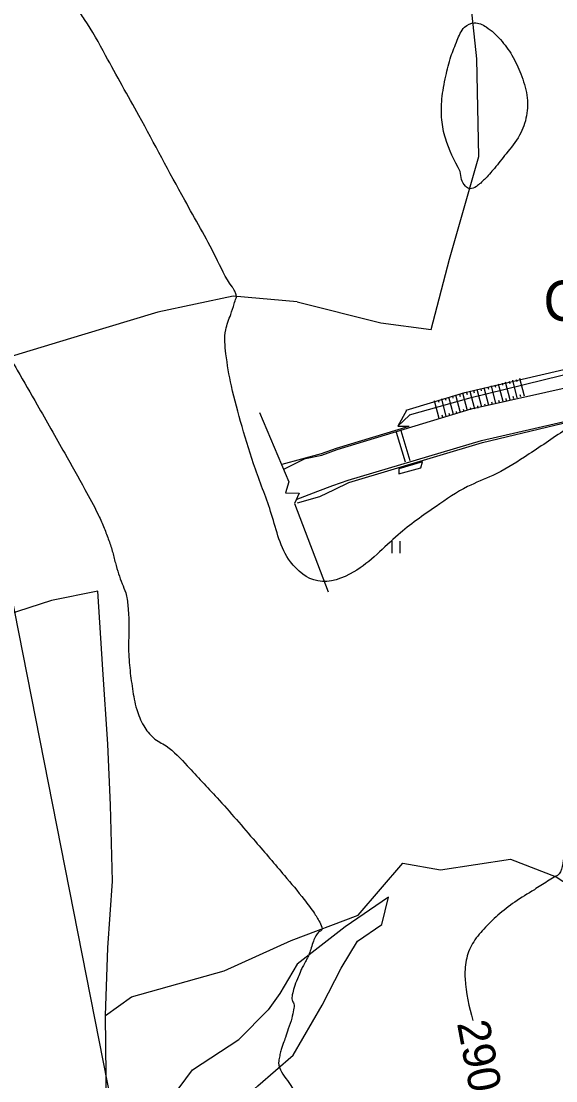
# Model space of a CAD drawing. Extents: x -475575 to -473225, y -1116053 to -1114104.
# Drawn here: x -474438.2 to -474372, y -1114570.2 to -1114439 of the extents above; entities that cross this region are included whole.
import ezdxf

# ---------------------------------------------------------------- set-up
doc = ezdxf.new("R2010")
doc.units = 0
for name, color, linetype in [('Budovy', 7, 'Continuous'), ('cesty', 7, 'Continuous'), ('hrana_P', 7, 'Continuous'), ('pam__tka', 7, 'Continuous'), ('TP_HS', 7, 'Continuous'), ('Vrstevnice_hlavni', 7, 'Continuous'), ('Vrstevnice_popis', 7, 'Continuous'), ('Vrstevnice_vedlejsi', 7, 'Continuous'), ('Vrstva_10', 7, 'Continuous')]:
    doc.layers.add(name, color=color, linetype=linetype)

msp = doc.modelspace()

# ---------------------------------------------------------------- linework, layer by layer
msp.add_lwpolyline([(-474182.626466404, -1115811.6046355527), (-473891.2432688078, -1115754.1169659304), (-474175.77819926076, -1114311.9173010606), (-474467.1613968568, -1114369.4049706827)], close=True)
at = {"layer": 'Budovy'}
msp.add_lwpolyline([(-474408.6644094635, -1114487.462002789), (-474405.0206297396, -1114496.0347098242), (-474405.46910377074, -1114497.4175296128), (-474403.7775642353, -1114497.4403683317), (-474404.3242316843, -1114498.727380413), (-474400.1589070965, -1114509.6549173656)], dxfattribs=at)
at = {"layer": 'cesty'}
for p, q in [((-474391.5530898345, -1114489.1814863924), (-474390.14101885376, -1114489.1419196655)), ((-474400.9560000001, -1114492.753), (-474399.05700000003, -1114492.0660000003)), ((-474402.9630000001, -1114493.158), (-474400.9560000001, -1114492.753)), ((-474402.9630000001, -1114493.158), (-474402.9630000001, -1114493.158)), ((-474399.402, -1114496.983), (-474397.609, -1114496.132)), ((-474401.18200000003, -1114497.8600000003), (-474399.402, -1114496.983)), ((-474403.96950800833, -1114498.639742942), (-474401.18200000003, -1114497.8600000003))]:
    msp.add_line(p, q, dxfattribs=at)
for points in [[(-474390.5118018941, -1114487.1961753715), (-474383.2441160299, -1114485.0014103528), (-474364.44700000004, -1114480.627)], [(-474364.32800000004, -1114481.217), (-474382.8100104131, -1114485.7461660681), (-474390.14775582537, -1114487.8018328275)], [(-474399.05700000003, -1114492.0660000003), (-474382.49493628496, -1114487.0226715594), (-474363.99100000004, -1114482.889)], [(-474380.28498984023, -1114486.5844812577), (-474380.8555120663, -1114484.4056765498)], [(-474380.41640151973, -1114484.2906950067), (-474380.3450862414, -1114484.5630455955)], [(-474379.40676874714, -1114486.3545181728), (-474379.9772909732, -1114484.1757134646)], [(-474379.5381804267, -1114484.0607319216), (-474379.4668651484, -1114484.3330825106)], [(-474378.528547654, -1114486.1245550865), (-474379.09906988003, -1114483.9457503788)], [(-474378.65995933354, -1114483.8307688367), (-474378.5886440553, -1114484.1031194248)], [(-474377.65032656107, -1114485.8945920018), (-474378.22084878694, -1114483.7157872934)], [(-474377.78173824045, -1114483.6008057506), (-474377.7104229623, -1114483.8731563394)], [(-474376.77210546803, -1114485.6646289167), (-474377.34262769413, -1114483.4858242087)], [(-474376.90351714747, -1114483.3708426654), (-474376.8322018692, -1114483.6431932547)], [(-474375.89388437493, -1114485.4346658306), (-474376.464406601, -1114483.2558611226)], [(-474385.6857280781, -1114485.6704735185), (-474385.61441279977, -1114485.9428241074)], [(-474384.6760953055, -1114487.7342966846), (-474385.2466175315, -1114485.5554919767)], [(-474384.80750698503, -1114485.4405104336), (-474384.7361917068, -1114485.7128610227)], [(-474383.7978742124, -1114487.5043335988), (-474384.3683964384, -1114485.3255288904)], [(-474383.92928589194, -1114485.2105473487), (-474383.8579706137, -1114485.4828979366)], [(-474382.9196531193, -1114487.2743705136), (-474383.49017534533, -1114485.0955658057)], [(-474383.05106479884, -1114484.9805842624), (-474382.9797495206, -1114485.2529348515)], [(-474382.0414320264, -1114487.0444074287), (-474382.6119542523, -1114484.8656027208)], [(-474382.17284370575, -1114484.7506211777), (-474382.1015284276, -1114485.0229717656)], [(-474381.16321093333, -1114486.8144443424), (-474381.73373315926, -1114484.6356396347)], [(-474381.29462261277, -1114484.5206580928), (-474381.2233073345, -1114484.7930086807)], [(-474378.0894371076, -1114486.0095735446), (-474378.16075238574, -1114485.7372229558)], [(-474377.2112160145, -1114485.7796104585), (-474377.28253129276, -1114485.5072598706)], [(-474376.3329949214, -1114485.5496473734), (-474376.40431019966, -1114485.2772967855)], [(-474397.715, -1114495.834), (-474381.1846396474, -1114490.937751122), (-474363.201, -1114486.811)], [(-474397.609, -1114496.132), (-474381.09452447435, -1114491.169170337), (-474363.188, -1114486.8730000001)], [(-474386.4325374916, -1114488.1942228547), (-474387.0030597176, -1114486.0154181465)], [(-474386.5639491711, -1114485.9004366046), (-474386.4926338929, -1114486.1727871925)], [(-474385.55431639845, -1114487.9642597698), (-474386.1248386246, -1114485.7854550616)], [(-474382.4805425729, -1114487.1593889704), (-474382.55185785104, -1114486.8870383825)], [(-474381.6023214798, -1114486.9294258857), (-474381.67363675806, -1114486.6570752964)], [(-474380.7241003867, -1114486.6994628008), (-474380.79541566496, -1114486.4271122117)], [(-474379.8458792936, -1114486.4694997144), (-474379.917194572, -1114486.1971491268)], [(-474378.9676582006, -1114486.2395366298), (-474379.0389734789, -1114485.9671860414)], [(-474390.4945073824, -1114487.2188734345), (-474391.5530898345, -1114489.1814863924), (-474390.12851488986, -1114487.8025076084)], [(-474385.9934269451, -1114488.0792413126), (-474386.06474222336, -1114487.8068907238)], [(-474385.11520585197, -1114487.8492782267), (-474385.1865211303, -1114487.5769276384)], [(-474384.236984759, -1114487.6193151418), (-474384.3083000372, -1114487.3469645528)], [(-474383.3587636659, -1114487.3893520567), (-474383.43007894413, -1114487.1170014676)], [(-474405.8515442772, -1114493.8510337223), (-474401.0100955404, -1114492.559884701), (-474399.1201915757, -1114491.8761753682), (-474390.14101885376, -1114489.1419196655)], [(-474399.57700000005, -1114496.507), (-474397.715, -1114495.834)], [(-474404.128962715, -1114498.2366301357), (-474401.43200000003, -1114497.199)], [(-474401.43200000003, -1114497.199), (-474399.57700000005, -1114496.507)]]:
    msp.add_lwpolyline(points, dxfattribs=at)
at = {"layer": 'hrana_P'}
msp.add_lwpolyline([(-474402.9630000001, -1114493.158), (-474405.61337955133, -1114494.4839191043)], dxfattribs=at)
at = {"layer": 'pam__tka'}
for p, q in [((-474390.6075392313, -1114493.6333155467), (-474391.7283912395, -1114489.9261577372)), ((-474390.0332159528, -1114493.459670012), (-474391.154067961, -1114489.7525122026))]:
    msp.add_line(p, q, dxfattribs=at)
msp.add_lwpolyline([(-474391.4259391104, -1114494.4299316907), (-474391.4259391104, -1114495.0529834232), (-474388.7172134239, -1114494.3364739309), (-474388.50816562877, -1114493.5888118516)], close=True, dxfattribs=at)
at = {"layer": 'Vrstevnice_hlavni'}
for points in [[(-474314.4652568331, -1114423.5624916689), (-474315.15, -1114426.169), (-474316.163, -1114431.774), (-474317.369, -1114436.945), (-474318.766, -1114441.6800000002), (-474320.35400000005, -1114445.9810000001), (-474321.972, -1114449.681), (-474323.617, -1114452.78), (-474325.291, -1114455.277), (-474326.74100000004, -1114457.9300000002), (-474327.967, -1114460.736), (-474328.96900000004, -1114463.698), (-474329.84400000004, -1114466.1400000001), (-474330.59300000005, -1114468.063), (-474331.215, -1114469.466), (-474332.08400000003, -1114471.237), (-474333.19800000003, -1114473.375), (-474334.559, -1114475.8800000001), (-474336.125, -1114478.272), (-474337.896, -1114480.55), (-474339.87200000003, -1114482.7140000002), (-474341.606, -1114484.4710000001), (-474343.097, -1114485.82), (-474344.34500000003, -1114486.761), (-474345.39900000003, -1114487.69), (-474346.25800000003, -1114488.605), (-474346.922, -1114489.5080000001), (-474348.744, -1114492.982), (-474351.72400000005, -1114499.027), (-474355.862, -1114507.6430000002), (-474358.802, -1114513.52), (-474360.543, -1114516.658), (-474361.086, -1114517.057), (-474361.549, -1114517.367), (-474361.93200000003, -1114517.5890000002), (-474362.234, -1114517.723), (-474362.69200000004, -1114518.027), (-474363.30600000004, -1114518.5010000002), (-474364.075, -1114519.145), (-474364.359, -1114519.9980000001), (-474364.157, -1114521.0590000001), (-474363.46900000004, -1114522.3290000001), (-474364.041, -1114525.543), (-474365.87200000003, -1114530.7), (-474368.962, -1114537.801), (-474371.03, -1114542.537), (-474372.07700000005, -1114544.908), (-474372.101, -1114544.915), (-474372.13, -1114544.928), (-474372.16400000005, -1114544.948), (-474372.20200000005, -1114544.975), (-474373.03500000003, -1114545.5050000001), (-474374.661, -1114546.538), (-474377.082, -1114548.074), (-474379.16500000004, -1114549.699), (-474380.91000000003, -1114551.414), (-474382.31700000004, -1114553.219), (-474383.09300000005, -1114555.2780000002), (-474383.239, -1114557.591), (-474382.271, -1114562.7280000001)], [(-474496.71900000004, -1114442.414), (-474488.08, -1114444.274), (-474485.004, -1114444.8660000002), (-474483.172, -1114445.12), (-474482.58300000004, -1114445.036), (-474481.96300000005, -1114444.972), (-474481.31200000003, -1114444.9270000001), (-474480.629, -1114444.9030000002), (-474479.207, -1114445.301), (-474477.044, -1114446.121), (-474474.14200000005, -1114447.364), (-474472.06200000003, -1114448.208), (-474470.804, -1114448.655), (-474470.369, -1114448.703), (-474467.59, -1114451.1330000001), (-474462.465, -1114455.9440000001), (-474454.99600000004, -1114463.136), (-474449.324, -1114468.739), (-474445.45, -1114472.754), (-474443.373, -1114475.181), (-474441.797, -1114477.129), (-474440.723, -1114478.598), (-474440.15, -1114479.588), (-474438.634, -1114482.234), (-474436.17500000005, -1114486.5350000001), (-474432.77300000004, -1114492.493), (-474430.272, -1114496.986), (-474428.67100000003, -1114500.017), (-474427.971, -1114501.583), (-474427.375, -1114503.117), (-474426.884, -1114504.619), (-474426.498, -1114506.088), (-474426.09300000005, -1114507.438), (-474425.669, -1114508.669), (-474425.226, -1114509.781), (-474424.945, -1114511.439), (-474424.826, -1114513.6430000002), (-474424.869, -1114516.392), (-474424.723, -1114519.071), (-474424.38700000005, -1114521.6800000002), (-474423.862, -1114524.218), (-474422.993, -1114526.242), (-474421.77900000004, -1114527.7510000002), (-474420.221, -1114528.746), (-474417.601, -1114531.217), (-474413.919, -1114535.163), (-474409.17500000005, -1114540.584), (-474405.582, -1114544.781), (-474403.14200000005, -1114547.754), (-474401.85400000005, -1114549.504), (-474401.12600000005, -1114550.762), (-474400.957, -1114551.529), (-474401.348, -1114551.8050000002), (-474401.696, -1114552.2680000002), (-474402, -1114552.919), (-474402.261, -1114553.757), (-474402.509, -1114554.453), (-474402.745, -1114555.006), (-474402.967, -1114555.416), (-474403.157, -1114555.7650000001), (-474403.31200000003, -1114556.051), (-474403.435, -1114556.276), (-474403.655, -1114556.786), (-474403.97400000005, -1114557.5820000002), (-474404.39200000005, -1114558.665), (-474404.607, -1114559.537), (-474404.62, -1114560.2010000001), (-474404.43000000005, -1114560.656), (-474404.44700000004, -1114561.402), (-474404.672, -1114562.441), (-474405.10400000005, -1114563.772), (-474405.455, -1114564.8190000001), (-474405.72500000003, -1114565.584), (-474405.91400000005, -1114566.066), (-474406.07200000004, -1114566.622), (-474406.2, -1114567.252), (-474406.298, -1114567.956), (-474405.21300000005, -1114570.172), (-474402.944, -1114573.899), (-474399.493, -1114579.138), (-474397.21800000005, -1114582.867), (-474396.119, -1114585.085), (-474396.19700000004, -1114585.7920000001), (-474396.238, -1114586.281), (-474396.243, -1114586.551), (-474396.212, -1114586.602), (-474396.19100000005, -1114586.638), (-474396.179, -1114586.6570000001), (-474396.177, -1114586.6600000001), (-474396.17600000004, -1114586.665), (-474396.17600000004, -1114586.673), (-474396.17600000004, -1114586.6840000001), (-474396.172, -1114586.689), (-474396.16400000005, -1114586.689), (-474396.152, -1114586.683), (-474395.809, -1114586.673), (-474395.136, -1114586.6600000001)]]:
    msp.add_spline(points, degree=3, dxfattribs=at)
at = {"layer": 'Vrstevnice_vedlejsi'}
for points in [[(-474327.64059357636, -1114407.3937584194), (-474328.603, -1114410.163), (-474331.498, -1114418.235), (-474335.64400000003, -1114429.118), (-474339.003, -1114437.261), (-474341.575, -1114442.664), (-474343.36100000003, -1114445.328), (-474344.701, -1114447.548), (-474345.596, -1114449.324), (-474346.047, -1114450.656), (-474347.707, -1114454.61), (-474350.57700000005, -1114461.188), (-474354.656, -1114470.389), (-474357.396, -1114476.561), (-474358.797, -1114479.703), (-474358.858, -1114479.815), (-474358.928, -1114479.922), (-474359.00800000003, -1114480.0250000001), (-474359.096, -1114480.122), (-474359.174, -1114480.2010000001), (-474359.24100000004, -1114480.261), (-474359.297, -1114480.304), (-474359.34500000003, -1114480.345), (-474359.38300000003, -1114480.386), (-474359.413, -1114480.4270000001), (-474359.495, -1114480.583), (-474359.629, -1114480.854), (-474359.814, -1114481.2410000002), (-474361.79500000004, -1114482.862), (-474365.571, -1114485.716), (-474371.14300000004, -1114489.8050000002), (-474375.891, -1114492.9880000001), (-474379.81700000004, -1114495.267), (-474382.92000000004, -1114496.6400000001), (-474386.819, -1114499.0890000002), (-474391.515, -1114502.6130000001), (-474397.00800000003, -1114507.212), (-474401.449, -1114508.3220000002), (-474404.83800000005, -1114505.943), (-474407.17500000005, -1114500.0760000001), (-474409.173, -1114494.493), (-474410.831, -1114489.1940000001), (-474412.14900000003, -1114484.1800000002), (-474412.82, -1114480.198), (-474412.846, -1114477.2480000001), (-474412.226, -1114475.331), (-474411.80000000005, -1114474.019), (-474411.568, -1114473.315), (-474411.531, -1114473.216), (-474411.527, -1114473.077), (-474411.55700000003, -1114472.897), (-474411.62, -1114472.676), (-474411.726, -1114472.4370000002), (-474411.87600000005, -1114472.179), (-474412.069, -1114471.9030000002), (-474414.08400000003, -1114468.235), (-474417.923, -1114461.176), (-474423.58300000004, -1114450.725), (-474427.711, -1114443.2680000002), (-474430.30500000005, -1114438.804), (-474431.36600000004, -1114437.334), (-474432.27, -1114436.107), (-474433.015, -1114435.1230000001), (-474433.603, -1114434.3830000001), (-474434.851, -1114432.753), (-474436.76200000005, -1114430.233)], [(-474383.846, -1114457.625), (-474383.178, -1114459.452), (-474382.62, -1114459.7680000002), (-474381.837, -1114459.486), (-474380.83, -1114458.607), (-474379.60400000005, -1114457.257), (-474378.158, -1114455.438), (-474376.492, -1114453.1500000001), (-474375.63300000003, -1114450.7380000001), (-474375.582, -1114448.203), (-474376.33900000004, -1114445.5450000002), (-474377.43000000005, -1114443.25), (-474378.853, -1114441.317), (-474380.61100000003, -1114439.747), (-474382.08900000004, -1114439.237), (-474383.287, -1114439.7850000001), (-474384.206, -1114441.392), (-474384.98000000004, -1114443.406), (-474385.61000000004, -1114445.827), (-474386.09400000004, -1114448.656), (-474386.114, -1114451.223), (-474385.668, -1114453.531), (-474383.846, -1114457.625)]]:
    msp.add_spline(points, degree=3, dxfattribs=at)
at = {"layer": 'Vrstva_10'}
for p, q in [((-474392.27, -1114504.888), (-474392.27, -1114503.388)), ((-474391.27, -1114504.888), (-474391.27, -1114503.388))]:
    msp.add_line(p, q, dxfattribs=at)
for points in [[(-474404.02400000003, -1114473.7820000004), (-474393.661, -1114476.3600000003), (-474387.417, -1114477.176), (-474385.14400000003, -1114468.503), (-474381.55000000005, -1114455.787), (-474381.76700000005, -1114443.676), (-474382.951, -1114432.844), (-474383.493, -1114429.956), (-474385.103, -1114417.665), (-474388.54600000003, -1114420.651), (-474397.50200000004, -1114425.7010000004), (-474407.87, -1114427.9240000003)], [(-474404.02400000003, -1114473.7820000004), (-474411.908, -1114473.081), (-474421.253, -1114475.057), (-474430.69700000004, -1114477.901), (-474441.75, -1114481.233)], [(-474427.598, -1114573.213), (-474427.733, -1114562.104), (-474424.52300000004, -1114559.79), (-474413.059, -1114556.5990000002), (-474404.738, -1114552.841), (-474396.454, -1114549.688), (-474390.919, -1114543.2380000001), (-474386.29000000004, -1114544.085), (-474377.59300000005, -1114542.759), (-474371.98000000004, -1114544.9300000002), (-474366.56700000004, -1114548.459), (-474359.955, -1114547.6130000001), (-474345.759, -1114541.411), (-474335.86500000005, -1114538.563), (-474329.00800000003, -1114535.638), (-474328.493, -1114530.1570000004), (-474329.129, -1114518.57), (-474331.081, -1114509.695), (-474333.027, -1114502.6200000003)], [(-474427.733, -1114562.104), (-474427.44800000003, -1114553.7240000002), (-474426.86500000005, -1114545.479), (-474427.101, -1114536.071), (-474427.43100000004, -1114528.509), (-474428.041, -1114519.288), (-474428.652, -1114509.5990000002), (-474434.385, -1114510.723), (-474444.386, -1114513.979), (-474455.407, -1114517.851), (-474467.32300000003, -1114521.7850000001), (-474478.579, -1114525.2850000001), (-474492.93000000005, -1114529.7720000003), (-474506.223, -1114534.162), (-474516.853, -1114537.6940000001), (-474531.14400000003, -1114542.479), (-474543.05600000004, -1114546.541), (-474553.771, -1114550.334), (-474566.64, -1114554.581), (-474576.78500000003, -1114558.074)], [(-474410.283, -1114585.9850000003), (-474411.821, -1114582.636), (-474413.24600000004, -1114578.3800000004), (-474413.03500000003, -1114574.517), (-474408.884, -1114570.801), (-474404.482, -1114567.013), (-474400.908, -1114560.817), (-474398.552, -1114556.2450000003), (-474396.541, -1114552.925), (-474393.515, -1114550.8560000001), (-474392.704, -1114547.4470000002)], [(-474392.704, -1114547.4470000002), (-474398.074, -1114551.152), (-474404.016, -1114555.752), (-474406.131, -1114559.384), (-474407.575, -1114561.4040000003)], [(-474419.576, -1114572.3360000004), (-474416.95300000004, -1114568.823), (-474411.226, -1114565.0790000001), (-474407.575, -1114561.4040000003)]]:
    msp.add_lwpolyline(points, dxfattribs=at)

# ---------------------------------------------------------------- texts
at = {"layer": 'TP_HS'}
msp.add_text('C30', height=4.999999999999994, rotation=359.9999938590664, dxfattribs=at).set_placement((-474373.5324333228, -1114476.1316815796))
at = {"layer": 'Vrstevnice_popis'}
msp.add_text(' 290 ', height=3.9999999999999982, rotation=280.6734119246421, dxfattribs=at).set_placement((-474384.51901148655, -1114561.6022106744))

doc.saveas('drawing.dxf')
